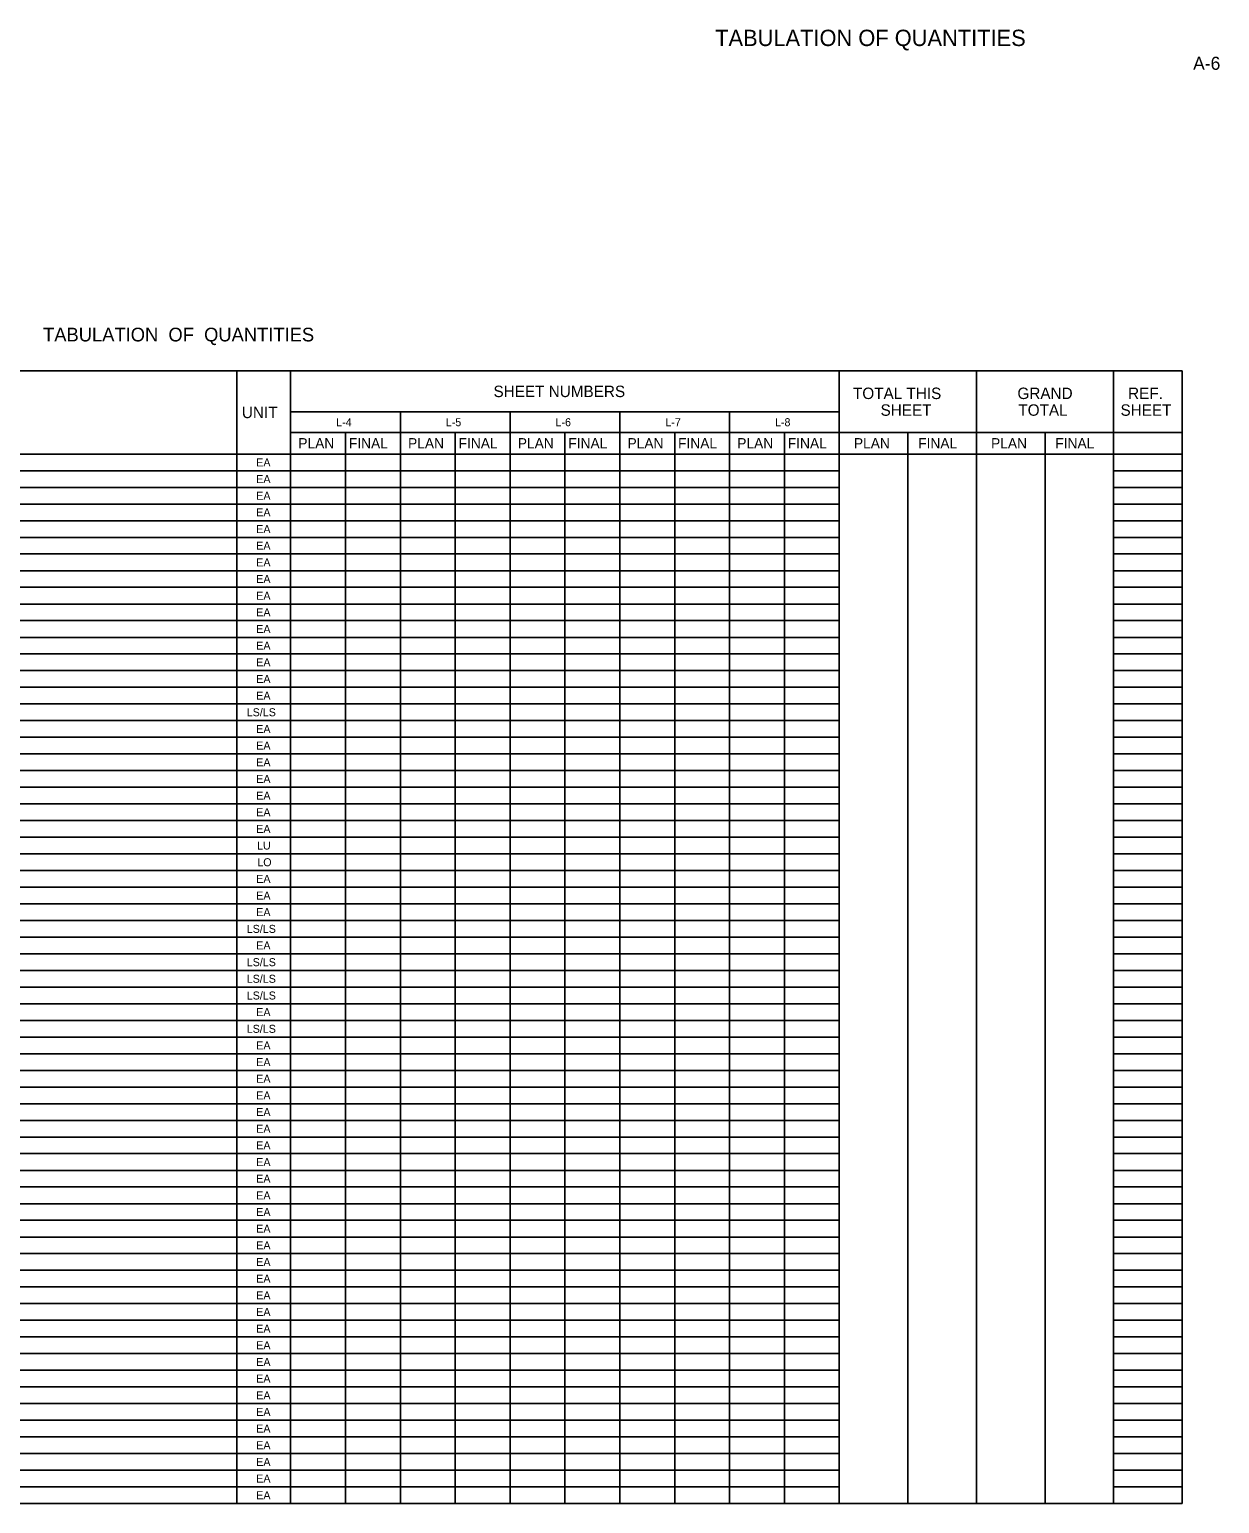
# Model space of a CAD drawing. Extents: x 56 to 1513, y -69 to 5602.
# Drawn here: x 602 to 1513, y 1190 to 2318 of the extents above; entities that cross this region are included whole.
import ezdxf

# ---------------------------------------------------------------- set-up
doc = ezdxf.new("R2010")
doc.units = 0
for name, color, linetype in [('Logo_dp', 7, 'Continuous'), ('SheetLines_dp', 7, 'Continuous'), ('TextCurveData', 7, 'Continuous'), ('TextMisc', 7, 'Continuous'), ('TextNotes', 7, 'Continuous')]:
    doc.layers.add(name, color=color, linetype=linetype)

msp = doc.modelspace()

# ---------------------------------------------------------------- linework, layer by layer
at = {"layer": 'SheetLines_dp'}
for p, q in [((56.1, 2056.9), (1431.6, 2056.9)), ((56.1, 2056.9), (1484.1, 2056.9)), ((760.4, 2056.9), (760.4, 1189.9)), ((760.4, 2056.9), (760.4, 1189.9)), ((801.6, 2056.9), (801.6, 2009.7)), ((801.6, 2056.9), (801.6, 1189.9)), ((1221.6, 2056.9), (1221.6, 1189.9)), ((1221.6, 2056.9), (1221.6, 1189.9)), ((1326.6, 2056.9), (1326.6, 1189.9)), ((1431.6, 2056.9), (1431.6, 1189.9)), ((1484.1, 2056.9), (1484.1, 1189.9)), ((801.6, 2025.4), (1221.6, 2025.4)), ((801.6, 2025.4), (1221.6, 2025.4)), ((885.6, 2025.4), (885.6, 1189.9)), ((885.6, 2025.4), (885.6, 1189.9)), ((969.6, 2025.4), (969.6, 1189.9)), ((969.6, 2025.4), (969.6, 2009.7)), ((1053.6, 2025.4), (1053.6, 1189.9)), ((1053.6, 2025.4), (1053.6, 2009.7)), ((1137.6, 2025.4), (1137.6, 1189.9)), ((1137.6, 2025.4), (1137.6, 1189.9)), ((801.6, 2009.7), (1484.1, 2009.7)), ((1221.6, 2009.7), (1484.1, 2009.7)), ((1326.6, 2009.7), (1326.6, 1189.9)), ((56.1, 1993.2), (1484.1, 1993.2)), ((801.6, 1993.2), (801.6, 1189.9)), ((801.6, 1993.2), (1484.1, 1993.2)), ((969.6, 1993.2), (969.6, 1189.9)), ((1053.6, 1993.2), (1053.6, 1189.9)), ((1431.6, 1993.2), (1431.6, 1189.9)), ((56.1, 1189.9), (1484.1, 1189.9))]:
    msp.add_line(p, q, dxfattribs=at)
at = {"layer": 'TextMisc'}
for p, q in [((843.6, 2009.7), (843.6, 1189.9)), ((843.6, 2009.7), (843.6, 1189.9)), ((927.6, 2009.7), (927.6, 1189.9)), ((927.6, 2009.7), (927.6, 1189.9)), ((969.6, 2009.7), (969.6, 1993.2)), ((1011.6, 2009.7), (1011.6, 1189.9)), ((1011.6, 2009.7), (1011.6, 1189.9)), ((1053.6, 2009.7), (1053.6, 1993.2)), ((1095.6, 2009.7), (1095.6, 1189.9)), ((1095.6, 2009.7), (1095.6, 1189.9)), ((1179.6, 2009.7), (1179.6, 1189.9)), ((1179.6, 2009.7), (1179.6, 1189.9)), ((1274.1, 2009.7), (1274.1, 1189.9)), ((1274.1, 2009.7), (1274.1, 1189.9)), ((1379.1, 2009.7), (1379.1, 1189.9)), ((1379.1, 2009.7), (1379.1, 1189.9)), ((56.1, 1993.2), (801.6, 1993.2)), ((56.1, 1980.4), (1221.6, 1980.4)), ((56.1, 1980.4), (1221.6, 1980.4)), ((1431.6, 1980.4), (1484.1, 1980.4)), ((1431.6, 1980.4), (1484.1, 1980.4)), ((56.1, 1967.7), (1221.6, 1967.7)), ((56.1, 1967.7), (1221.6, 1967.7)), ((1431.6, 1967.7), (1484.1, 1967.7)), ((1431.6, 1967.7), (1484.1, 1967.7)), ((56.1, 1954.9), (1221.6, 1954.9)), ((56.1, 1954.9), (1221.6, 1954.9)), ((1431.6, 1954.9), (1484.1, 1954.9)), ((1431.6, 1954.9), (1484.1, 1954.9)), ((56.1, 1942.2), (1221.6, 1942.2)), ((56.1, 1942.2), (1221.6, 1942.2)), ((1431.6, 1942.2), (1484.1, 1942.2)), ((1431.6, 1942.2), (1484.1, 1942.2)), ((56.1, 1929.4), (1221.6, 1929.4)), ((56.1, 1929.4), (1221.6, 1929.4)), ((1431.6, 1929.4), (1484.1, 1929.4)), ((1431.6, 1929.4), (1484.1, 1929.4)), ((56.1, 1916.7), (1221.6, 1916.7)), ((56.1, 1916.7), (1221.6, 1916.7)), ((1431.6, 1916.7), (1484.1, 1916.7)), ((1431.6, 1916.7), (1484.1, 1916.7)), ((56.1, 1903.9), (1221.6, 1903.9)), ((56.1, 1903.9), (1221.6, 1903.9)), ((1431.6, 1903.9), (1484.1, 1903.9)), ((1431.6, 1903.9), (1484.1, 1903.9)), ((56.1, 1891.2), (1221.6, 1891.2)), ((56.1, 1891.2), (1221.6, 1891.2)), ((1431.6, 1891.2), (1484.1, 1891.2)), ((1431.6, 1891.2), (1484.1, 1891.2)), ((56.1, 1878.4), (1221.6, 1878.4)), ((56.1, 1878.4), (1221.6, 1878.4)), ((1431.6, 1878.4), (1484.1, 1878.4)), ((1431.6, 1878.4), (1484.1, 1878.4)), ((56.1, 1865.7), (1221.6, 1865.7)), ((56.1, 1865.7), (1221.6, 1865.7)), ((1431.6, 1865.7), (1484.1, 1865.7)), ((1431.6, 1865.7), (1484.1, 1865.7)), ((56.1, 1852.9), (1221.6, 1852.9)), ((56.1, 1852.9), (1221.6, 1852.9)), ((1431.6, 1852.9), (1484.1, 1852.9)), ((1431.6, 1852.9), (1484.1, 1852.9)), ((56.1, 1840.2), (1221.6, 1840.2)), ((56.1, 1840.2), (1221.6, 1840.2)), ((1431.6, 1840.2), (1484.1, 1840.2)), ((1431.6, 1840.2), (1484.1, 1840.2)), ((56.1, 1827.4), (1221.6, 1827.4)), ((56.1, 1827.4), (1221.6, 1827.4)), ((1431.6, 1827.4), (1484.1, 1827.4)), ((1431.6, 1827.4), (1484.1, 1827.4)), ((56.1, 1814.7), (1221.6, 1814.7)), ((56.1, 1814.7), (1221.6, 1814.7)), ((1431.6, 1814.7), (1484.1, 1814.7)), ((1431.6, 1814.7), (1484.1, 1814.7)), ((56.1, 1801.9), (1221.6, 1801.9)), ((56.1, 1801.9), (1221.6, 1801.9)), ((1431.6, 1801.9), (1484.1, 1801.9)), ((1431.6, 1801.9), (1484.1, 1801.9)), ((56.1, 1789.2), (1221.6, 1789.2)), ((56.1, 1789.2), (1221.6, 1789.2)), ((1431.6, 1789.2), (1484.1, 1789.2)), ((1431.6, 1789.2), (1484.1, 1789.2)), ((56.1, 1776.4), (1221.6, 1776.4)), ((56.1, 1776.4), (1221.6, 1776.4)), ((1431.6, 1776.4), (1484.1, 1776.4)), ((1431.6, 1776.4), (1484.1, 1776.4)), ((56.1, 1763.7), (1221.6, 1763.7)), ((56.1, 1763.7), (1221.6, 1763.7)), ((1431.6, 1763.7), (1484.1, 1763.7)), ((1431.6, 1763.7), (1484.1, 1763.7)), ((56.1, 1750.9), (1221.6, 1750.9)), ((56.1, 1750.9), (1221.6, 1750.9)), ((1431.6, 1750.9), (1484.1, 1750.9)), ((1431.6, 1750.9), (1484.1, 1750.9)), ((56.1, 1738.2), (1221.6, 1738.2)), ((56.1, 1738.2), (1221.6, 1738.2)), ((1431.6, 1738.2), (1484.1, 1738.2)), ((1431.6, 1738.2), (1484.1, 1738.2)), ((56.1, 1725.4), (1221.6, 1725.4)), ((56.1, 1725.4), (1221.6, 1725.4)), ((1431.6, 1725.4), (1484.1, 1725.4)), ((1431.6, 1725.4), (1484.1, 1725.4)), ((56.1, 1712.7), (1221.6, 1712.7)), ((56.1, 1712.7), (1221.6, 1712.7)), ((1431.6, 1712.7), (1484.1, 1712.7)), ((1431.6, 1712.7), (1484.1, 1712.7)), ((56.1, 1699.9), (1221.6, 1699.9)), ((56.1, 1699.9), (1221.6, 1699.9)), ((1431.6, 1699.9), (1484.1, 1699.9)), ((1431.6, 1699.9), (1484.1, 1699.9)), ((56.1, 1687.2), (1221.6, 1687.2)), ((56.1, 1687.2), (1221.6, 1687.2)), ((1431.6, 1687.2), (1484.1, 1687.2)), ((1431.6, 1687.2), (1484.1, 1687.2)), ((56.1, 1674.4), (1221.6, 1674.4)), ((56.1, 1674.4), (1221.6, 1674.4)), ((1431.6, 1674.4), (1484.1, 1674.4)), ((1431.6, 1674.4), (1484.1, 1674.4)), ((56.1, 1661.7), (1221.6, 1661.7)), ((56.1, 1661.7), (1221.6, 1661.7)), ((1431.6, 1661.7), (1484.1, 1661.7)), ((1431.6, 1661.7), (1484.1, 1661.7)), ((56.1, 1648.9), (1221.6, 1648.9)), ((56.1, 1648.9), (1221.6, 1648.9)), ((1431.6, 1648.9), (1484.1, 1648.9)), ((1431.6, 1648.9), (1484.1, 1648.9)), ((56.1, 1636.2), (1221.6, 1636.2)), ((56.1, 1636.2), (1221.6, 1636.2)), ((1431.6, 1636.2), (1484.1, 1636.2)), ((1431.6, 1636.2), (1484.1, 1636.2)), ((56.1, 1623.4), (1221.6, 1623.4)), ((56.1, 1623.4), (1221.6, 1623.4)), ((1431.6, 1623.4), (1484.1, 1623.4)), ((1431.6, 1623.4), (1484.1, 1623.4)), ((56.1, 1610.7), (1221.6, 1610.7)), ((56.1, 1610.7), (1221.6, 1610.7)), ((1431.6, 1610.7), (1484.1, 1610.7)), ((1431.6, 1610.7), (1484.1, 1610.7)), ((56.1, 1597.9), (1221.6, 1597.9)), ((56.1, 1597.9), (1221.6, 1597.9)), ((1431.6, 1597.9), (1484.1, 1597.9)), ((1431.6, 1597.9), (1484.1, 1597.9)), ((56.1, 1585.2), (1221.6, 1585.2)), ((56.1, 1585.2), (1221.6, 1585.2)), ((1431.6, 1585.2), (1484.1, 1585.2)), ((1431.6, 1585.2), (1484.1, 1585.2)), ((56.1, 1572.4), (1221.6, 1572.4)), ((56.1, 1572.4), (1221.6, 1572.4)), ((1431.6, 1572.4), (1484.1, 1572.4)), ((1431.6, 1572.4), (1484.1, 1572.4)), ((56.1, 1559.7), (1221.6, 1559.7)), ((56.1, 1559.7), (1221.6, 1559.7)), ((1431.6, 1559.7), (1484.1, 1559.7)), ((1431.6, 1559.7), (1484.1, 1559.7)), ((56.1, 1546.9), (1221.6, 1546.9)), ((56.1, 1546.9), (1221.6, 1546.9)), ((1431.6, 1546.9), (1484.1, 1546.9)), ((1431.6, 1546.9), (1484.1, 1546.9)), ((56.1, 1534.2), (1221.6, 1534.2)), ((56.1, 1534.2), (1221.6, 1534.2)), ((1431.6, 1534.2), (1484.1, 1534.2)), ((1431.6, 1534.2), (1484.1, 1534.2)), ((56.1, 1521.4), (1221.6, 1521.4)), ((56.1, 1521.4), (1221.6, 1521.4)), ((1431.6, 1521.4), (1484.1, 1521.4)), ((1431.6, 1521.4), (1484.1, 1521.4)), ((56.1, 1508.7), (1221.6, 1508.7)), ((56.1, 1508.7), (1221.6, 1508.7)), ((1431.6, 1508.7), (1484.1, 1508.7)), ((1431.6, 1508.7), (1484.1, 1508.7)), ((56.1, 1495.9), (1221.6, 1495.9)), ((56.1, 1495.9), (1221.6, 1495.9)), ((1431.6, 1495.9), (1484.1, 1495.9)), ((1431.6, 1495.9), (1484.1, 1495.9)), ((56.1, 1483.2), (1221.6, 1483.2)), ((56.1, 1483.2), (1221.6, 1483.2)), ((1431.6, 1483.2), (1484.1, 1483.2)), ((1431.6, 1483.2), (1484.1, 1483.2)), ((56.1, 1470.4), (1221.6, 1470.4)), ((56.1, 1470.4), (1221.6, 1470.4)), ((1431.6, 1470.4), (1484.1, 1470.4)), ((1431.6, 1470.4), (1484.1, 1470.4)), ((56.1, 1457.7), (1221.6, 1457.7)), ((56.1, 1457.7), (1221.6, 1457.7)), ((1431.6, 1457.7), (1484.1, 1457.7)), ((1431.6, 1457.7), (1484.1, 1457.7)), ((56.1, 1444.9), (1221.6, 1444.9)), ((56.1, 1444.9), (1221.6, 1444.9)), ((1431.6, 1444.9), (1484.1, 1444.9)), ((1431.6, 1444.9), (1484.1, 1444.9)), ((56.1, 1432.2), (1221.6, 1432.2)), ((56.1, 1432.2), (1221.6, 1432.2)), ((1431.6, 1432.2), (1484.1, 1432.2)), ((1431.6, 1432.2), (1484.1, 1432.2)), ((56.1, 1419.4), (1221.6, 1419.4)), ((56.1, 1419.4), (1221.6, 1419.4)), ((1431.6, 1419.4), (1484.1, 1419.4)), ((1431.6, 1419.4), (1484.1, 1419.4)), ((56.1, 1406.7), (1221.6, 1406.7)), ((56.1, 1406.7), (1221.6, 1406.7)), ((1431.6, 1406.7), (1484.1, 1406.7)), ((1431.6, 1406.7), (1484.1, 1406.7)), ((56.1, 1393.9), (1221.6, 1393.9)), ((56.1, 1393.9), (1221.6, 1393.9)), ((1431.6, 1393.9), (1484.1, 1393.9)), ((1431.6, 1393.9), (1484.1, 1393.9)), ((56.1, 1381.2), (1221.6, 1381.2)), ((56.1, 1381.2), (1221.6, 1381.2)), ((1431.6, 1381.2), (1484.1, 1381.2)), ((1431.6, 1381.2), (1484.1, 1381.2)), ((56.1, 1368.4), (1221.6, 1368.4)), ((56.1, 1368.4), (1221.6, 1368.4)), ((1431.6, 1368.4), (1484.1, 1368.4)), ((1431.6, 1368.4), (1484.1, 1368.4)), ((56.1, 1355.7), (1221.6, 1355.7)), ((56.1, 1355.7), (1221.6, 1355.7)), ((1431.6, 1355.7), (1484.1, 1355.7)), ((1431.6, 1355.7), (1484.1, 1355.7)), ((56.1, 1342.9), (1221.6, 1342.9)), ((56.1, 1342.9), (1221.6, 1342.9)), ((1431.6, 1342.9), (1484.1, 1342.9)), ((1431.6, 1342.9), (1484.1, 1342.9)), ((56.1, 1330.2), (1221.6, 1330.2)), ((56.1, 1330.2), (1221.6, 1330.2)), ((1431.6, 1330.2), (1484.1, 1330.2)), ((1431.6, 1330.2), (1484.1, 1330.2)), ((56.1, 1317.4), (1221.6, 1317.4)), ((56.1, 1317.4), (1221.6, 1317.4)), ((1431.6, 1317.4), (1484.1, 1317.4)), ((1431.6, 1317.4), (1484.1, 1317.4)), ((56.1, 1304.7), (1221.6, 1304.7)), ((56.1, 1304.7), (1221.6, 1304.7)), ((1431.6, 1304.7), (1484.1, 1304.7)), ((1431.6, 1304.7), (1484.1, 1304.7)), ((56.1, 1291.9), (1221.6, 1291.9)), ((56.1, 1291.9), (1221.6, 1291.9)), ((1431.6, 1291.9), (1484.1, 1291.9)), ((1431.6, 1291.9), (1484.1, 1291.9)), ((56.1, 1279.2), (1221.6, 1279.2)), ((56.1, 1279.2), (1221.6, 1279.2)), ((1431.6, 1279.2), (1484.1, 1279.2)), ((1431.6, 1279.2), (1484.1, 1279.2)), ((56.1, 1266.4), (1221.6, 1266.4)), ((56.1, 1266.4), (1221.6, 1266.4)), ((1431.6, 1266.4), (1484.1, 1266.4)), ((1431.6, 1266.4), (1484.1, 1266.4)), ((56.1, 1253.7), (1221.6, 1253.7)), ((56.1, 1253.7), (1221.6, 1253.7)), ((1431.6, 1253.7), (1484.1, 1253.7)), ((1431.6, 1253.7), (1484.1, 1253.7)), ((56.1, 1240.9), (1221.6, 1240.9)), ((56.1, 1240.9), (1221.6, 1240.9)), ((1431.6, 1240.9), (1484.1, 1240.9)), ((1431.6, 1240.9), (1484.1, 1240.9)), ((56.1, 1228.2), (1221.6, 1228.2)), ((56.1, 1228.2), (1221.6, 1228.2)), ((1431.6, 1228.2), (1484.1, 1228.2)), ((1431.6, 1228.2), (1484.1, 1228.2)), ((56.1, 1215.4), (1221.6, 1215.4)), ((56.1, 1215.4), (1221.6, 1215.4)), ((1431.6, 1215.4), (1484.1, 1215.4)), ((1431.6, 1215.4), (1484.1, 1215.4)), ((56.1, 1202.7), (1221.6, 1202.7)), ((56.1, 1202.7), (1221.6, 1202.7)), ((1431.6, 1202.7), (1484.1, 1202.7)), ((1431.6, 1202.7), (1484.1, 1202.7))]:
    msp.add_line(p, q, dxfattribs=at)

# ---------------------------------------------------------------- texts
at = {"layer": 'Logo_dp'}
msp.add_text('A-6', height=10, dxfattribs=at).set_placement((1492.5, 2287.3))
at = {"layer": 'TextCurveData'}
for s, height, p in [('TABULATION  OF  QUANTITIES', 10.5, (612.1, 2079.4)), ('SHEET NUMBERS', 8.75, (956.9, 2036.8)), ('TOTAL THIS', 8.75, (1232.1, 2035.3)), ('GRAND', 8.75, (1358, 2035.3)), ('REF.', 8.75, (1442.7, 2035.3)), ('SHEET', 8.75, (1253.2, 2022.5)), ('TOTAL', 8.75, (1358.7, 2022.5)), ('SHEET', 8.75, (1436.9, 2022.5)), ('UNIT', 8.75, (764.3, 2020.7)), ('L-4', 6.12, (836.5, 2014.5)), ('L-5', 6.12, (920.4, 2014.5)), ('L-6', 6.12, (1004.4, 2014.5)), ('L-7', 6.12, (1088.5, 2014.5)), ('L-8', 6.12, (1172.4, 2014.5)), ('PLAN', 7.88, (807.5, 1997.5)), ('FINAL', 7.88, (846.2, 1997.5)), ('PLAN', 7.88, (891.5, 1997.5)), ('FINAL', 7.88, (930.2, 1997.5)), ('PLAN', 7.88, (975.5, 1997.5)), ('FINAL', 7.88, (1014.2, 1997.5)), ('PLAN', 7.88, (1059.5, 1997.5)), ('FINAL', 7.88, (1098.2, 1997.5)), ('PLAN', 7.88, (1143.5, 1997.5)), ('FINAL', 7.88, (1182.2, 1997.5)), ('PLAN', 7.88, (1232.8, 1997.5)), ('FINAL', 7.88, (1282, 1997.5)), ('PLAN', 7.88, (1337.8, 1997.5)), ('FINAL', 7.88, (1387, 1997.5)), ('EA', 6.12, (775.3, 1983.7)), ('EA', 6.12, (775.3, 1971)), ('EA', 6.12, (775.3, 1958.2)), ('EA', 6.12, (775.3, 1945.5)), ('EA', 6.12, (775.3, 1932.7)), ('EA', 6.12, (775.3, 1920)), ('EA', 6.12, (775.3, 1907.2)), ('EA', 6.12, (775.3, 1894.5)), ('EA', 6.12, (775.3, 1881.7)), ('EA', 6.12, (775.3, 1869)), ('EA', 6.12, (775.3, 1856.2)), ('EA', 6.12, (775.3, 1843.5)), ('EA', 6.12, (775.3, 1830.7)), ('EA', 6.12, (775.3, 1818)), ('EA', 6.12, (775.3, 1805.2)), ('LS/LS', 6.12, (768, 1792.5)), ('EA', 6.12, (775.3, 1779.7)), ('EA', 6.12, (775.3, 1767)), ('EA', 6.12, (775.3, 1754.2)), ('EA', 6.12, (775.3, 1741.5)), ('EA', 6.12, (775.3, 1728.7)), ('EA', 6.12, (775.3, 1716)), ('EA', 6.12, (775.3, 1703.2)), ('LU', 6.12, (775.9, 1690.5)), ('LO', 6.12, (776.1, 1677.7)), ('EA', 6.12, (775.3, 1665)), ('EA', 6.12, (775.3, 1652.2)), ('EA', 6.12, (775.3, 1639.5)), ('LS/LS', 6.12, (768, 1626.7)), ('EA', 6.12, (775.3, 1614)), ('LS/LS', 6.12, (768, 1601.2)), ('LS/LS', 6.12, (768, 1588.5)), ('LS/LS', 6.12, (768, 1575.7)), ('EA', 6.12, (775.3, 1563)), ('LS/LS', 6.12, (768, 1550.2)), ('EA', 6.12, (775.3, 1537.5)), ('EA', 6.12, (775.3, 1524.7)), ('EA', 6.12, (775.3, 1512)), ('EA', 6.12, (775.3, 1499.2)), ('EA', 6.12, (775.3, 1486.5)), ('EA', 6.12, (775.3, 1473.7)), ('EA', 6.12, (775.3, 1461)), ('EA', 6.12, (775.3, 1448.2)), ('EA', 6.12, (775.3, 1435.5)), ('EA', 6.12, (775.3, 1422.7)), ('EA', 6.12, (775.3, 1410)), ('EA', 6.12, (775.3, 1397.2)), ('EA', 6.12, (775.3, 1384.5)), ('EA', 6.12, (775.3, 1371.7)), ('EA', 6.12, (775.3, 1359)), ('EA', 6.12, (775.3, 1346.2)), ('EA', 6.12, (775.3, 1333.5)), ('EA', 6.12, (775.3, 1320.7)), ('EA', 6.12, (775.3, 1308)), ('EA', 6.12, (775.3, 1295.2)), ('EA', 6.12, (775.3, 1282.5)), ('EA', 6.12, (775.3, 1269.7)), ('EA', 6.12, (775.3, 1257)), ('EA', 6.12, (775.3, 1244.2)), ('EA', 6.12, (775.3, 1231.5)), ('EA', 6.12, (775.3, 1218.7)), ('EA', 6.12, (775.3, 1206)), ('EA', 6.12, (775.3, 1193.2))]:
    msp.add_text(s, height=height, dxfattribs=at).set_placement(p)
at = {"layer": 'TextNotes'}
msp.add_text('TABULATION OF QUANTITIES ', height=12.5, dxfattribs=at).set_placement((1126.6, 2305.5))

doc.saveas('drawing.dxf')
